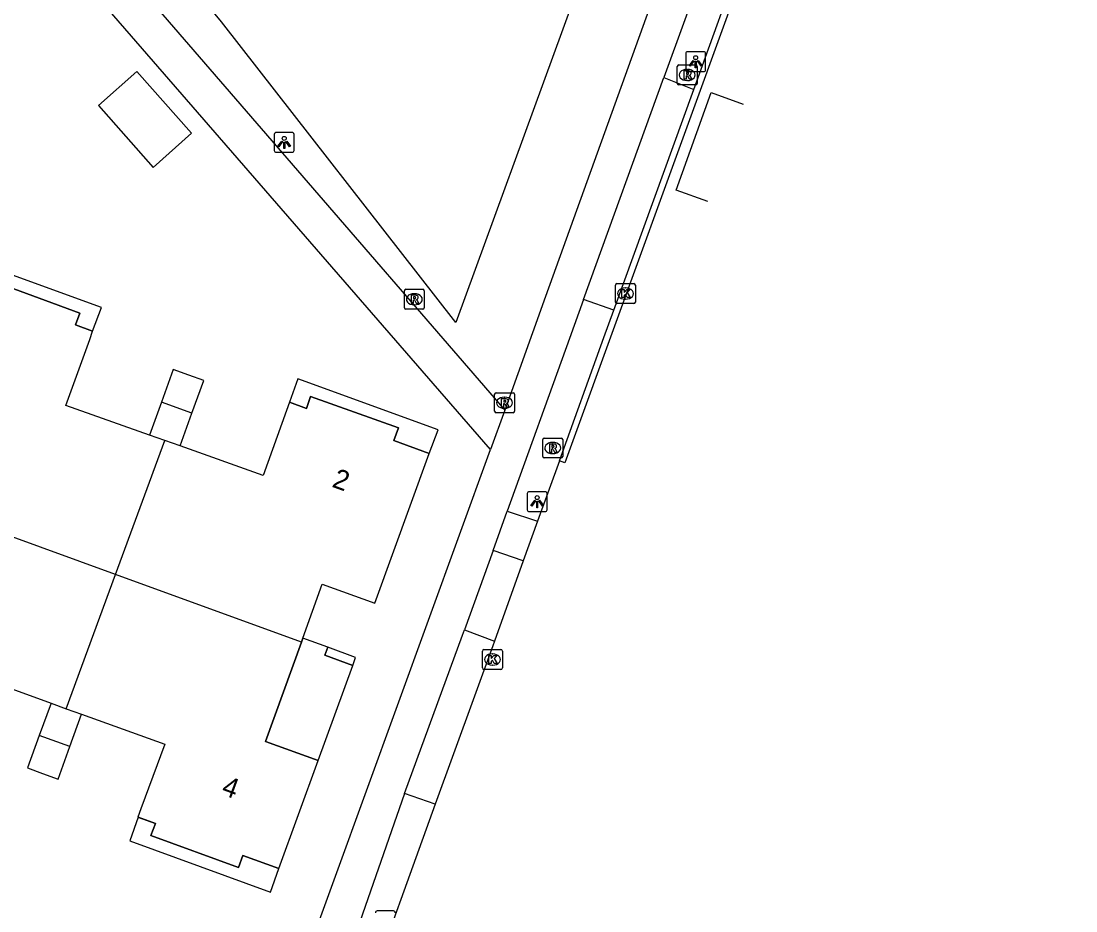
# Model space of a CAD drawing. Extents: x 155888 to 156864, y 383882 to 384671.
# Drawn here: x 156761.9 to 156814.9, y 384194 to 384238.7 of the extents above; entities that cross this region are included whole.
import ezdxf

# ---------------------------------------------------------------- set-up
doc = ezdxf.new("R2010")
doc.units = 0
for name, color, linetype in [('IMGEO_Groenvoorziening', 7, 'Continuous'), ('IMGEO_Kolk', 7, 'Continuous'), ('IMGEO_Lichtpunt', 7, 'Continuous'), ('IMGEO_Pand', 7, 'Continuous'), ('IMGEO_Pand_nummerreeks', 7, 'Continuous'), ('IMGEO_Pand_overbouw', 7, 'Continuous'), ('IMGEO_Parkeervlak_open', 7, 'Continuous'), ('IMGEO_Rijbaan_lokaal_open', 7, 'Continuous'), ('IMGEO_Rioolput', 7, 'Continuous'), ('IMGEO_Voetpad_open', 7, 'Continuous')]:
    doc.layers.add(name, color=color, linetype=linetype)

msp = doc.modelspace()

# ---------------------------------------------------------------- linework, layer by layer
at = {"layer": 'IMGEO_Groenvoorziening'}
msp.add_lwpolyline([(156783.739, 384223.517), (156771.979, 384238.616), (156764.865, 384247.181), (156770.963, 384261.409), (156774.012, 384263.006), (156787.223, 384274.838), (156796.805, 384283.331), (156798.547, 384282.75), (156798.837, 384277.088), (156794.482, 384252.988), (156783.739, 384223.517)], dxfattribs=at)
at = {"layer": 'IMGEO_Kolk'}
for p, q in [((156791.751, 384224.55), (156791.751, 384225.402)), ((156791.826, 384225.476), (156792.678, 384225.476)), ((156792.239, 384225.256), (156792.264, 384225.256)), ((156792.752, 384225.402), (156792.752, 384224.55)), ((156792.262, 384224.696), (156792.237, 384224.696)), ((156792.678, 384224.476), (156791.826, 384224.476)), ((156785.075, 384206.181), (156785.075, 384207.033)), ((156785.15, 384207.107), (156786.002, 384207.107)), ((156786.076, 384207.033), (156786.076, 384206.181)), ((156785.563, 384206.887), (156785.588, 384206.887)), ((156786.002, 384206.107), (156785.15, 384206.107)), ((156785.586, 384206.327), (156785.561, 384206.327))]:
    msp.add_line(p, q, dxfattribs=at)
for points in [[(156791.751, 384224.55), (156791.751, 384225.402)], [(156791.826, 384225.476), (156792.678, 384225.476)], [(156792.072, 384225.176), (156792.195, 384225.176), (156792.195, 384225.025), (156792.325, 384225.176), (156792.489, 384225.176), (156792.343, 384225.025), (156792.496, 384224.776), (156792.344, 384224.776), (156792.259, 384224.94), (156792.195, 384224.873), (156792.195, 384224.776), (156792.072, 384224.776), (156792.072, 384225.176)], [(156792.752, 384225.402), (156792.752, 384224.55)], [(156792.678, 384224.476), (156791.826, 384224.476)], [(156785.075, 384206.181), (156785.075, 384207.033)], [(156785.15, 384207.107), (156786.002, 384207.107)], [(156786.076, 384207.033), (156786.076, 384206.181)], [(156785.396, 384206.807), (156785.519, 384206.807), (156785.519, 384206.656), (156785.649, 384206.807), (156785.813, 384206.807), (156785.667, 384206.656), (156785.82, 384206.407), (156785.668, 384206.407), (156785.583, 384206.571), (156785.519, 384206.504), (156785.519, 384206.407), (156785.396, 384206.407), (156785.396, 384206.807)], [(156786.002, 384206.107), (156785.15, 384206.107)]]:
    msp.add_lwpolyline(points, dxfattribs=at)
for centre, start, end in [((156791.828, 384225.4), 91.552, 178.448), ((156791.828, 384225.4), 91.552, 178.448), ((156792.676, 384225.4), 1.552, 88.448), ((156792.676, 384225.4), 1.552, 88.448), ((156791.828, 384224.552), 181.552, 268.448), ((156791.828, 384224.552), 181.552, 268.448), ((156792.676, 384224.552), 271.552, 358.448), ((156792.676, 384224.552), 271.552, 358.448), ((156785.152, 384207.031), 91.552, 178.448), ((156785.152, 384207.031), 91.552, 178.448), ((156786, 384207.031), 1.552, 88.448), ((156786, 384207.031), 1.552, 88.448), ((156785.152, 384206.183), 181.552, 268.448), ((156785.152, 384206.183), 181.552, 268.448), ((156786, 384206.183), 271.552, 358.448), ((156786, 384206.183), 271.552, 358.448)]:
    msp.add_arc(centre, 0.0765, start, end, dxfattribs=at)
for centre, major_axis, ratio, start_param, end_param in [((156792.238, 384224.976), (-0.387, 0.002), 0.722429, 4.712389, 7.853982), ((156792.263, 384224.976), (-0.39, 0.002), 0.717154, 1.570796, 4.712389), ((156785.562, 384206.607), (-0.387, 0.002), 0.722429, 4.712389, 7.853982), ((156785.587, 384206.607), (-0.39, 0.002), 0.717154, 1.570796, 4.712389)]:
    msp.add_ellipse(centre, major_axis=major_axis, ratio=ratio, start_param=start_param, end_param=end_param, dxfattribs=at)
at = {"layer": 'IMGEO_Lichtpunt'}
for p, q in [((156795.28, 384237.017), (156795.28, 384236.21)), ((156795.28, 384237.017), (156795.28, 384236.21)), ((156796.182, 384237.112), (156795.374, 384237.112)), ((156796.182, 384237.112), (156795.374, 384237.112)), ((156796.276, 384236.21), (156796.276, 384237.017)), ((156796.276, 384236.21), (156796.276, 384237.017)), ((156795.374, 384236.116), (156796.182, 384236.116)), ((156795.374, 384236.116), (156796.182, 384236.116)), ((156774.62, 384232.966), (156774.62, 384232.159)), ((156774.62, 384232.966), (156774.62, 384232.159)), ((156775.522, 384233.061), (156774.714, 384233.061)), ((156775.522, 384233.061), (156774.714, 384233.061)), ((156775.616, 384232.159), (156775.616, 384232.966)), ((156775.616, 384232.159), (156775.616, 384232.966)), ((156774.714, 384232.065), (156775.522, 384232.065)), ((156774.714, 384232.065), (156775.522, 384232.065)), ((156788.224, 384215.028), (156787.416, 384215.028)), ((156788.224, 384215.028), (156787.416, 384215.028)), ((156787.322, 384214.933), (156787.322, 384214.126)), ((156787.322, 384214.933), (156787.322, 384214.126)), ((156788.318, 384214.126), (156788.318, 384214.933)), ((156788.318, 384214.126), (156788.318, 384214.933)), ((156787.416, 384214.032), (156788.224, 384214.032)), ((156787.416, 384214.032), (156788.224, 384214.032)), ((156780.603, 384193.988), (156779.795, 384193.988)), ((156780.603, 384193.988), (156779.795, 384193.988))]:
    msp.add_line(p, q, dxfattribs=at)
for points in [[(156795.654, 384236.681), (156795.693, 384236.653), (156795.505, 384236.391), (156795.467, 384236.418), (156795.654, 384236.681)], [(156795.866, 384236.653), (156795.904, 384236.68), (156796.091, 384236.418), (156796.052, 384236.39), (156795.866, 384236.653)], [(156795.756, 384236.633), (156795.803, 384236.633), (156795.803, 384236.311), (156795.756, 384236.311), (156795.756, 384236.633)], [(156774.994, 384232.63), (156775.033, 384232.602), (156774.845, 384232.34), (156774.807, 384232.367), (156774.994, 384232.63)], [(156775.096, 384232.582), (156775.143, 384232.582), (156775.143, 384232.26), (156775.096, 384232.26), (156775.096, 384232.582)], [(156775.206, 384232.602), (156775.244, 384232.629), (156775.431, 384232.367), (156775.392, 384232.339), (156775.206, 384232.602)], [(156787.696, 384214.597), (156787.735, 384214.569), (156787.547, 384214.307), (156787.509, 384214.334), (156787.696, 384214.597)], [(156787.798, 384214.549), (156787.845, 384214.549), (156787.845, 384214.227), (156787.798, 384214.227), (156787.798, 384214.549)], [(156787.908, 384214.569), (156787.946, 384214.596), (156788.133, 384214.334), (156788.094, 384214.306), (156787.908, 384214.569)]]:
    msp.add_lwpolyline(points, dxfattribs=at)
for centre in [(156795.779, 384236.815), (156775.119, 384232.764), (156787.821, 384214.731)]:
    msp.add_circle(centre, 0.0994, dxfattribs=at)
for centre, start, end in [((156795.374, 384237.017), 90, 180), ((156795.374, 384237.017), 90, 180), ((156796.182, 384237.017), 0, 90), ((156796.182, 384237.017), 0, 90), ((156795.374, 384236.21), 180, 270), ((156795.374, 384236.21), 180, 270), ((156796.182, 384236.21), 270, 0), ((156796.182, 384236.21), 270, 360), ((156774.714, 384232.966), 90, 180), ((156774.714, 384232.966), 90, 180), ((156775.522, 384232.966), 0, 90), ((156775.522, 384232.966), 0, 90), ((156774.714, 384232.159), 180, 270), ((156774.714, 384232.159), 180, 270), ((156775.522, 384232.159), 270, 0), ((156775.522, 384232.159), 270, 360), ((156787.416, 384214.933), 90, 180), ((156787.416, 384214.933), 90, 180), ((156788.224, 384214.933), 0, 90), ((156788.224, 384214.933), 0, 90), ((156787.416, 384214.126), 180, 270), ((156787.416, 384214.126), 180, 270), ((156788.224, 384214.126), 270, 0), ((156788.224, 384214.126), 270, 360), ((156779.795, 384193.893), 90, 180), ((156779.795, 384193.893), 90, 180), ((156780.603, 384193.893), 0, 90), ((156780.603, 384193.893), 0, 90)]:
    msp.add_arc(centre, 0.0946, start, end, dxfattribs=at)
at = {"layer": 'IMGEO_Pand'}
for points in [[(156768.539, 384231.308), (156770.47, 384233.019), (156767.724, 384236.117), (156765.793, 384234.406), (156768.539, 384231.308)], [(156768.361, 384217.87), (156764.158, 384219.36), (156765.354, 384222.677), (156765.499, 384223.093), (156764.642, 384223.397), (156764.862, 384223.998), (156760.447, 384225.619), (156760.242, 384225.007), (156758.454, 384225.666), (156756.48, 384220.212), (156759.132, 384219.252), (156757.31, 384214.273)], [(156770.49, 384218.966), (156771.083, 384220.606), (156770.335, 384220.876), (156769.55, 384221.16), (156768.956, 384219.515)], [(156775.981, 384207.474), (156776.053, 384207.675), (156777.026, 384210.391), (156779.677, 384209.43), (156782.405, 384216.954), (156780.628, 384217.598), (156780.861, 384218.227), (156776.439, 384219.807), (156776.237, 384219.198), (156775.387, 384219.517), (156775.238, 384219.103), (156774.063, 384215.849), (156769.897, 384217.326)], [(156768.956, 384219.515), (156768.361, 384217.87)], [(156770.49, 384218.966), (156768.956, 384219.515)], [(156769.897, 384217.326), (156770.49, 384218.966)], [(156766.654, 384210.87), (156769.129, 384217.598)], [(156769.129, 384217.598), (156768.361, 384217.87)], [(156769.897, 384217.326), (156769.129, 384217.598)], [(156757.31, 384214.273), (156757.233, 384214.064), (156756.245, 384211.331), (156753.597, 384212.302), (156750.84, 384204.786), (156752.643, 384204.125), (156752.438, 384203.569), (156756.83, 384201.993), (156757.043, 384202.582), (156757.914, 384202.26), (156758.067, 384202.673), (156759.269, 384205.913), (156763.411, 384204.415)], [(156766.654, 384210.87), (156757.31, 384214.273)], [(156764.177, 384204.138), (156766.654, 384210.87)], [(156775.981, 384207.474), (156766.654, 384210.87)], [(156764.944, 384203.861), (156769.119, 384202.351), (156767.922, 384199.105), (156767.772, 384198.691), (156768.651, 384198.374), (156768.431, 384197.773), (156772.83, 384196.168), (156773.049, 384196.77), (156774.854, 384196.115), (156776.825, 384201.531), (156774.175, 384202.495), (156775.981, 384207.474)], [(156777.304, 384207.221), (156777.157, 384206.817), (156778.558, 384206.31), (156778.705, 384206.714), (156777.304, 384207.221)], [(156763.411, 384204.415), (156762.823, 384202.788)], [(156763.411, 384204.415), (156764.177, 384204.138)], [(156764.177, 384204.138), (156764.944, 384203.861)], [(156764.355, 384202.234), (156764.944, 384203.861)], [(156762.823, 384202.788), (156762.234, 384201.161), (156762.982, 384200.891), (156763.767, 384200.607), (156764.355, 384202.234)], [(156764.355, 384202.234), (156762.823, 384202.788)]]:
    msp.add_lwpolyline(points, dxfattribs=at)
at = {"layer": 'IMGEO_Pand_overbouw'}
for points in [[(156758.454, 384225.666), (156760.242, 384225.007), (156760.447, 384225.619), (156764.862, 384223.998), (156764.642, 384223.397), (156765.499, 384223.093), (156765.938, 384224.271), (156758.878, 384226.839)], [(156782.405, 384216.954), (156782.853, 384218.141), (156775.812, 384220.698), (156775.387, 384219.517), (156776.237, 384219.198), (156776.439, 384219.807), (156780.861, 384218.227), (156780.628, 384217.598)], [(156778.558, 384206.31), (156777.157, 384206.817), (156777.304, 384207.221), (156776.053, 384207.675), (156775.981, 384207.474), (156774.175, 384202.495), (156776.825, 384201.531)], [(156767.788, 384198.685), (156767.362, 384197.513), (156774.425, 384194.936), (156774.854, 384196.115), (156773.049, 384196.77), (156772.83, 384196.168), (156768.431, 384197.773), (156768.651, 384198.374)]]:
    msp.add_lwpolyline(points, close=True, dxfattribs=at)
at = {"layer": 'IMGEO_Parkeervlak_open'}
for points in [[(156794.179, 384235.818), (156795.693, 384235.224)], [(156791.676, 384224.143), (156790.149, 384224.671)]]:
    msp.add_lwpolyline(points, dxfattribs=at)
at = {"layer": 'IMGEO_Rijbaan_lokaal_open'}
for points in [[(156814.871, 384287.065), (156789.212, 384216.482), (156788.935, 384216.582)], [(156795.693, 384235.224), (156800.812, 384249.42)], [(156791.676, 384224.143), (156795.693, 384235.224)], [(156794.793, 384230.171), (156796.564, 384235.066), (156798.157, 384234.489)], [(156796.393, 384229.598), (156794.793, 384230.171)], [(156788.935, 384216.582), (156791.165, 384222.772), (156791.676, 384224.143)], [(156788.935, 384216.582), (156787.843, 384213.551)], [(156787.843, 384213.551), (156787.126, 384211.559)], [(156787.126, 384211.559), (156785.671, 384207.521)], [(156781.165, 384199.889), (156784.069, 384207.825), (156784.166, 384208.095)], [(156784.166, 384208.095), (156785.671, 384207.521)], [(156785.671, 384207.521), (156785.587, 384207.288), (156782.705, 384199.351)], [(156782.705, 384199.351), (156781.165, 384199.889)], [(156782.705, 384199.351), (156779.028, 384189.177)]]:
    msp.add_lwpolyline(points, dxfattribs=at)
at = {"layer": 'IMGEO_Rioolput'}
for p, q in [((156794.855, 384235.522), (156794.855, 384236.374)), ((156794.93, 384236.448), (156795.782, 384236.448)), ((156795.343, 384236.228), (156795.368, 384236.228)), ((156795.856, 384236.374), (156795.856, 384235.522)), ((156795.366, 384235.668), (156795.341, 384235.668)), ((156795.782, 384235.448), (156794.93, 384235.448)), ((156781.152, 384224.262), (156781.152, 384225.114)), ((156781.227, 384225.188), (156782.079, 384225.188)), ((156782.153, 384225.114), (156782.153, 384224.262)), ((156781.64, 384224.968), (156781.665, 384224.968)), ((156782.079, 384224.188), (156781.227, 384224.188)), ((156781.663, 384224.408), (156781.638, 384224.408)), ((156785.683, 384219.068), (156785.683, 384219.92)), ((156785.758, 384219.994), (156786.61, 384219.994)), ((156786.171, 384219.774), (156786.196, 384219.774)), ((156786.684, 384219.92), (156786.684, 384219.068)), ((156786.194, 384219.214), (156786.169, 384219.214)), ((156786.61, 384218.994), (156785.758, 384218.994)), ((156788.101, 384216.796), (156788.101, 384217.648)), ((156788.176, 384217.722), (156789.028, 384217.722)), ((156789.102, 384217.648), (156789.102, 384216.796)), ((156788.589, 384217.502), (156788.614, 384217.502)), ((156789.028, 384216.722), (156788.176, 384216.722)), ((156788.612, 384216.942), (156788.587, 384216.942))]:
    msp.add_line(p, q, dxfattribs=at)
for points in [[(156794.855, 384235.522), (156794.855, 384236.374)], [(156794.93, 384236.448), (156795.782, 384236.448)], [(156795.444, 384236.146), (156795.192, 384236.148), (156795.192, 384235.748)], [(156795.856, 384236.374), (156795.856, 384235.522)], [(156795.192, 384235.748), (156795.316, 384235.748), (156795.316, 384235.91), (156795.327, 384235.91)], [(156795.37, 384236.067), (156795.316, 384236.067), (156795.316, 384235.986)], [(156795.316, 384235.986), (156795.368, 384235.986)], [(156795.374, 384235.881), (156795.445, 384235.748), (156795.585, 384235.748), (156795.52, 384235.874)], [(156795.782, 384235.448), (156794.93, 384235.448)], [(156781.152, 384224.262), (156781.152, 384225.114)], [(156781.227, 384225.188), (156782.079, 384225.188)], [(156782.153, 384225.114), (156782.153, 384224.262)], [(156781.741, 384224.886), (156781.489, 384224.888), (156781.489, 384224.488)], [(156781.489, 384224.488), (156781.613, 384224.488), (156781.613, 384224.65), (156781.624, 384224.65)], [(156781.667, 384224.807), (156781.613, 384224.807), (156781.613, 384224.726)], [(156781.613, 384224.726), (156781.665, 384224.726)], [(156781.671, 384224.621), (156781.742, 384224.488), (156781.882, 384224.488), (156781.817, 384224.614)], [(156782.079, 384224.188), (156781.227, 384224.188)], [(156785.683, 384219.068), (156785.683, 384219.92)], [(156785.758, 384219.994), (156786.61, 384219.994)], [(156786.684, 384219.92), (156786.684, 384219.068)], [(156786.272, 384219.692), (156786.02, 384219.694), (156786.02, 384219.294)], [(156786.02, 384219.294), (156786.144, 384219.294), (156786.144, 384219.456), (156786.155, 384219.456)], [(156786.198, 384219.613), (156786.144, 384219.613), (156786.144, 384219.532)], [(156786.144, 384219.532), (156786.196, 384219.532)], [(156786.202, 384219.427), (156786.273, 384219.294), (156786.413, 384219.294), (156786.348, 384219.42)], [(156786.61, 384218.994), (156785.758, 384218.994)], [(156788.101, 384216.796), (156788.101, 384217.648)], [(156788.176, 384217.722), (156789.028, 384217.722)], [(156789.102, 384217.648), (156789.102, 384216.796)], [(156788.69, 384217.42), (156788.438, 384217.422), (156788.438, 384217.022)], [(156788.438, 384217.022), (156788.562, 384217.022), (156788.562, 384217.184), (156788.573, 384217.184)], [(156788.616, 384217.341), (156788.562, 384217.341), (156788.562, 384217.26)], [(156788.562, 384217.26), (156788.614, 384217.26)], [(156788.62, 384217.155), (156788.691, 384217.022), (156788.831, 384217.022), (156788.766, 384217.148)], [(156789.028, 384216.722), (156788.176, 384216.722)]]:
    msp.add_lwpolyline(points, dxfattribs=at)
for centre, radius, start, end in [((156794.932, 384236.372), 0.0765, 91.552, 178.448), ((156794.932, 384236.372), 0.0765, 91.552, 178.448), ((156795.443, 384236.036), 0.109, 350.3612, 89.416), ((156795.78, 384236.372), 0.0765, 1.552, 88.448), ((156795.78, 384236.372), 0.0765, 1.552, 88.448), ((156795.326, 384235.857), 0.0533, 26.0293, 88.6989), ((156795.352, 384236.175), 0.19, 274.7715, 282.9687), ((156795.376, 384235.971), 0.0964, 77.0061, 93.1865), ((156795.39, 384236.028), 0.0378, 276.6634, 79.6772), ((156795.441, 384236.036), 0.112, 277.5842, 350.9817), ((156795.425, 384235.821), 0.108, 29.5134, 73.7905), ((156794.932, 384235.524), 0.0765, 181.552, 268.448), ((156794.932, 384235.524), 0.0765, 181.552, 268.448), ((156795.78, 384235.524), 0.0765, 271.552, 358.448), ((156795.78, 384235.524), 0.0765, 271.552, 358.448), ((156781.229, 384225.112), 0.0765, 91.552, 178.448), ((156781.229, 384225.112), 0.0765, 91.552, 178.448), ((156782.077, 384225.112), 0.0765, 1.552, 88.448), ((156782.077, 384225.112), 0.0765, 1.552, 88.448), ((156781.623, 384224.597), 0.0533, 26.0293, 88.6989), ((156781.649, 384224.915), 0.19, 274.7715, 282.9687), ((156781.673, 384224.711), 0.0964, 77.0061, 93.1865), ((156781.687, 384224.768), 0.0378, 276.6634, 79.6772), ((156781.74, 384224.776), 0.109, 350.3612, 89.416), ((156781.738, 384224.776), 0.112, 277.5842, 350.9817), ((156781.722, 384224.561), 0.108, 29.5134, 73.7905), ((156781.229, 384224.264), 0.0765, 181.552, 268.448), ((156781.229, 384224.264), 0.0765, 181.552, 268.448), ((156782.077, 384224.264), 0.0765, 271.552, 358.448), ((156782.077, 384224.264), 0.0765, 271.552, 358.448), ((156785.76, 384219.918), 0.0765, 91.552, 178.448), ((156785.76, 384219.918), 0.0765, 91.552, 178.448), ((156786.608, 384219.918), 0.0765, 1.552, 88.448), ((156786.608, 384219.918), 0.0765, 1.552, 88.448), ((156786.154, 384219.403), 0.0533, 26.0293, 88.6989), ((156786.18, 384219.721), 0.19, 274.7715, 282.9687), ((156786.204, 384219.517), 0.0964, 77.0061, 93.1865), ((156786.218, 384219.574), 0.0378, 276.6634, 79.6772), ((156786.271, 384219.582), 0.109, 350.3612, 89.416), ((156786.269, 384219.582), 0.112, 277.5842, 350.9817), ((156786.253, 384219.367), 0.108, 29.5134, 73.7905), ((156785.76, 384219.07), 0.0765, 181.552, 268.448), ((156785.76, 384219.07), 0.0765, 181.552, 268.448), ((156786.608, 384219.07), 0.0765, 271.552, 358.448), ((156786.608, 384219.07), 0.0765, 271.552, 358.448), ((156788.178, 384217.646), 0.0765, 91.552, 178.448), ((156788.178, 384217.646), 0.0765, 91.552, 178.448), ((156789.026, 384217.646), 0.0765, 1.552, 88.448), ((156789.026, 384217.646), 0.0765, 1.552, 88.448), ((156788.572, 384217.131), 0.0533, 26.0293, 88.6989), ((156788.598, 384217.449), 0.19, 274.7715, 282.9687), ((156788.622, 384217.245), 0.0964, 77.0061, 93.1865), ((156788.636, 384217.302), 0.0378, 276.6634, 79.6772), ((156788.689, 384217.31), 0.109, 350.3612, 89.416), ((156788.687, 384217.31), 0.112, 277.5842, 350.9817), ((156788.671, 384217.095), 0.108, 29.5134, 73.7905), ((156788.178, 384216.798), 0.0765, 181.552, 268.448), ((156788.178, 384216.798), 0.0765, 181.552, 268.448), ((156789.026, 384216.798), 0.0765, 271.552, 358.448), ((156789.026, 384216.798), 0.0765, 271.552, 358.448)]:
    msp.add_arc(centre, radius, start, end, dxfattribs=at)
for centre, major_axis, ratio, start_param, end_param in [((156795.342, 384235.948), (-0.387, 0.002), 0.722429, 4.712389, 7.853982), ((156795.367, 384235.948), (-0.39, 0.002), 0.717154, 1.570796, 4.712389), ((156781.639, 384224.688), (-0.387, 0.002), 0.722429, 4.712389, 7.853982), ((156781.664, 384224.688), (-0.39, 0.002), 0.717154, 1.570796, 4.712389), ((156786.17, 384219.494), (-0.387, 0.002), 0.722429, 4.712389, 7.853982), ((156786.195, 384219.494), (-0.39, 0.002), 0.717154, 1.570796, 4.712389), ((156788.588, 384217.222), (-0.387, 0.002), 0.722429, 4.712389, 7.853982), ((156788.613, 384217.222), (-0.39, 0.002), 0.717154, 1.570796, 4.712389)]:
    msp.add_ellipse(centre, major_axis=major_axis, ratio=ratio, start_param=start_param, end_param=end_param, dxfattribs=at)
at = {"layer": 'IMGEO_Voetpad_open'}
for points in [[(156813.189, 384294.055), (156806.307, 384274.964), (156788.246, 384224.829), (156786.203, 384219.126)], [(156799.325, 384249.945), (156794.179, 384235.818)], [(156762.806, 384246.175), (156786.203, 384219.126)], [(156785.484, 384217.152), (156762.028, 384244.15)], [(156790.149, 384224.671), (156794.179, 384235.818)], [(156790.149, 384224.671), (156789.445, 384222.723), (156786.318, 384214.059)], [(156786.203, 384219.126), (156785.484, 384217.152)], [(156727.592, 384057.564), (156727.82, 384058.123), (156737.823, 384085.568), (156752.766, 384127.202), (156785.484, 384217.152)], [(156785.606, 384212.084), (156786.318, 384214.059)], [(156786.318, 384214.059), (156787.843, 384213.551)], [(156785.606, 384212.084), (156784.166, 384208.095)], [(156787.126, 384211.559), (156785.606, 384212.084)], [(156781.165, 384199.889), (156777.613, 384189.688)]]:
    msp.add_lwpolyline(points, dxfattribs=at)

# ---------------------------------------------------------------- texts
at = {"layer": 'IMGEO_Pand_nummerreeks'}
for s, rotation, p in [('2', 340.0439, (156777.472, 384215.288)), ('4', 339.6543, (156771.917, 384199.857))]:
    msp.add_text(s, height=1, rotation=rotation, dxfattribs=at).set_placement(p)

doc.saveas('drawing.dxf')
